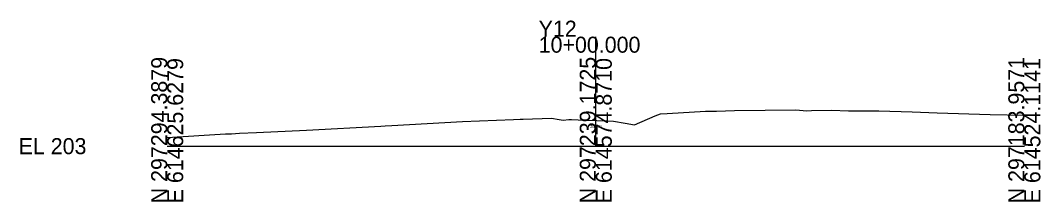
# Model space of a CAD drawing. Extents: x 517327 to 517505, y 114839 to 117367.
# Drawn here: x 517326.7 to 517505.2, y 114838.7 to 114870.3 of the extents above; entities that cross this region are included whole.
import ezdxf

# ---------------------------------------------------------------- set-up
doc = ezdxf.new("R2010")
doc.units = 0
for name, color, linetype in [('Exist XS Ground Line', 7, 'Continuous'), ('Old_Level_59', 7, 'Continuous'), ('Old_Level_63', 7, 'Continuous')]:
    doc.layers.add(name, color=color, linetype=linetype)

msp = doc.modelspace()

# ---------------------------------------------------------------- linework, layer by layer
at = {"layer": 'Exist XS Ground Line'}
for p, q in [((517448.48, 114854.48), (517451.64, 114854.61)), ((517451.64, 114854.61), (517462.39, 114854.74)), ((517462.39, 114854.74), (517464.29, 114854.55)), ((517464.29, 114854.55), (517465.09, 114854.59)), ((517465.09, 114854.59), (517468.64, 114854.63)), ((517468.64, 114854.63), (517471.61, 114854.56)), ((517471.61, 114854.56), (517475.55, 114854.56)), ((517404.06, 114852.68), (517412.96, 114853.03)), ((517412.96, 114853.03), (517414.11, 114853.07)), ((517414.11, 114853.07), (517414.68, 114853.09)), ((517414.68, 114853.09), (517419.63, 114853.25)), ((517419.63, 114853.25), (517420.96, 114853)), ((517420.96, 114853), (517421.66, 114852.9)), ((517421.66, 114852.9), (517422.62, 114853.01)), ((517422.62, 114853.01), (517423.1, 114853)), ((517423.1, 114853), (517424.29, 114852.96)), ((517424.29, 114852.96), (517425.5, 114852.92)), ((517425.5, 114852.92), (517427.57, 114852.87)), ((517427.57, 114852.87), (517429.38, 114852.79)), ((517429.38, 114852.79), (517430.49, 114852.73)), ((517434.13, 114852.09), (517437.73, 114853.69)), ((517437.73, 114853.69), (517438.69, 114854.04)), ((517438.69, 114854.04), (517439.87, 114854.08)), ((517439.87, 114854.08), (517446.54, 114854.47)), ((517446.54, 114854.47), (517448.48, 114854.48)), ((517475.55, 114854.56), (517476.33, 114854.54)), ((517476.33, 114854.54), (517476.92, 114854.53)), ((517476.92, 114854.53), (517482.75, 114854.34)), ((517482.75, 114854.34), (517487.09, 114854.19)), ((517487.09, 114854.19), (517496.36, 114853.89)), ((517496.36, 114853.89), (517502.36, 114853.79)), ((517368.01, 114850.77), (517376.72, 114851.18)), ((517376.72, 114851.18), (517389.73, 114851.88)), ((517389.73, 114851.88), (517390.52, 114851.92)), ((517390.52, 114851.92), (517391.66, 114851.98)), ((517391.66, 114851.98), (517404.06, 114852.68)), ((517430.49, 114852.73), (517432.5, 114852.36)), ((517432.5, 114852.36), (517434.13, 114852.09)), ((517352.36, 114849.85), (517362.54, 114850.51)), ((517362.54, 114850.51), (517363.1, 114850.5)), ((517363.1, 114850.5), (517363.61, 114850.51)), ((517363.61, 114850.51), (517364.99, 114850.62)), ((517364.99, 114850.62), (517368.01, 114850.77))]:
    msp.add_line(p, q, dxfattribs=at)
at = {"layer": 'Old_Level_63'}
for p, q in [((517427.36, 114848.36), (517427.36, 114867.5)), ((517352.36, 114848.36), (517427.36, 114848.36)), ((517427.36, 114848.36), (517502.36, 114848.36))]:
    msp.add_line(p, q, dxfattribs=at)

# ---------------------------------------------------------------- texts
at = {"layer": 'Old_Level_59'}
msp.add_text('207.51', height=0.5, dxfattribs=at).set_placement((517426.38, 114851.52))
at = {"layer": 'Old_Level_63'}
for s, p in [('Y12', (517417.36, 114867.5)), ('10+00.000', (517417.37, 114864.7)), ('EL 203', (517326.36, 114846.96))]:
    msp.add_text(s, height=2.8, dxfattribs=at).set_placement(p)
for s, p in [('N 297294.3879', (517352.36, 114838.36)), ('E 614625.6279', (517355.16, 114838.36)), ('N 297239.1725', (517427.36, 114838.37)), ('E 614574.8710', (517430.16, 114838.37)), ('N 297183.9571', (517502.36, 114838.36)), ('E 614524.1141', (517505.16, 114838.36))]:
    msp.add_text(s, height=2.8, rotation=90, dxfattribs=at).set_placement(p)

doc.saveas('drawing.dxf')
